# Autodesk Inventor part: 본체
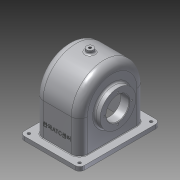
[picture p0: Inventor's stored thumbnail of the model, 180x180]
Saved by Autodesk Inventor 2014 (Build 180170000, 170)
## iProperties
Created: 2016-01
Part Number: 본체
Material: Aluminum 6061
Document SubType Name: Modeling
Designer: user
Density: 2.71 g/cm^3
Appearance: Aluminum - Flat
Mass: 812.573 g
Surface Area: 1007.61 cm^2
Volume: 299.842 cm^3
Author: user
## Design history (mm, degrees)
sketch "Sketch1"
  geometry: 1 further point
sketch "Sketch2"
  geometry: L1 (-57, 4)-(-57, -60); L2 (-57, -60)-(57, -60); L3 (57, -60)-(57, 4); A1 r 57 centre (0, 4) between (-57, 4) and (57, 4); 1 further point
  constraints: 6 end point, 2 perpendicular, 2 point on circle, 2 tangent, 1 centre point, 1 vertical, 1 vertical alignment
  dimensions: "d1" = 114 diameter of A1; "d3" = 60 distance from line of L2 point (0, 0); "d4" = 64 distance from line of L2 A1.centre
extrude "Extrusion1" new body sketch "Sketch2" stored distance "d5" = 77; taper "d6" = 0 deg
sketch "Sketch3"
  geometry: C1 r 31 at (0, 0); 1 further point
  constraints: 1 centre point, 1 coincident
  dimensions: "d7" = 62 diameter of C1
extrude "Extrusion2" join sketch "Sketch3" distance "d8" = 10; taper "d9" = 0 deg
workplane "Work Plane1"
sketch "Sketch4"
  geometry: C1 r 6 at (0, 0); 1 further point
  constraints: 1 centre point, 1 coincident
  dimensions: "d11" = 12 diameter of C1
extrude "Extrusion3" join sketch "Sketch4" stored distance "d12" = 6; taper "d13" = 0 deg
sketch "Sketch5"
  geometry: L1 (-13.5, 13)-(90.5, 13); L2 (90.5, 13)-(90.5, -127); L3 (90.5, -127)-(-13.5, -127); L4 (-13.5, -127)-(-13.5, 13); L5 (-13.5, 13)-(90.5, -127); L6 (90.5, 13)-(-13.5, -127); 1 further point
  constraints: 12 end point, 2 midpoint, 2 parallel, 1 horizontal, 1 perpendicular
  dimensions: "d14" = 104 distance of L1.start L1.end; "d15" = 140 distance of L1.end L2.end
extrude "Extrusion4" join sketch "Sketch5" distance "d16" = 7; taper "d17" = 0 deg
sketch "Sketch6"
  geometry: L1 (-57, -53)-(-57, 4) reference; L2 (57, 4)-(57, -53) reference; L3 (70, -60)-(-70, -60) reference; L4 (-51, -60)-(-51, 4); L5 (51, 4)-(51, -60); L6 (-51, -60)-(51, -60); A1 r 57 centre (0, 4) between (57, 4) and (-57, 4) reference; A2 r 51 centre (0, 4) between (51, 4) and (-51, 4); 1 further point
  constraints: 6 end point, 2 point on circle, 2 point on line, 1 centre point, 1 collinear
  dimensions: "d18" = 6 radial gap between concentric circles of A2 A1; "d19" = 6 distance between parallel lines of L4 L1; "d20" = 6 distance between parallel lines of L2 L5
extrude "Extrusion5" cut sketch "Sketch6" stored distance "d21" = 67; taper "d22" = 0 deg
sketch "Sketch7"
  geometry: C1 r 28 at (0, 0); 1 further point
  constraints: 1 centre point, 1 coincident
  dimensions: "d23" = 56 diameter of C1
extrude "Extrusion6" join sketch "Sketch7" distance "d24" = 14; taper "d25" = 0 deg
feature "FaceDraft1" dims angle "d26" = 40 deg
sketch "Sketch9"
  geometry: C1 r 20 at (0, 0); 1 further point
  constraints: 1 centre point, 1 coincident
  dimensions: "d27" = 40 diameter of C1
extrude "Extrusion7" cut sketch "Sketch9" distance "d28" = 16; taper "d29" = 0 deg
sketch "Sketch10"
  geometry: L1 (33.5, 39.747)-(19.5, 28) reference; L2 (38.5, 37.416)-(35.5, 34.899); L3 (38.5, 4)-(38.5, 61) reference; L4 (38.5, 37.416)-(38.5, 0); L5 (38.5, 0)-(35.5, 0); L6 (35.5, 0)-(35.5, 34.899); 1 further point
  constraints: 8 end point, 2 parallel, 2 point on line, 1 horizontal alignment, 1 perpendicular
  dimensions: "d30" = 5 distance between parallel lines of L2 L1; "d31" = 3 distance between parallel lines of L4 L6
revolve "Revolution1" sketch "Sketch10" stored, may be unused: angle "d32" = 90 deg
sketch "Sketch11"
  geometry: C1 r 20 at (0, 0); 1 further point
  constraints: 1 centre point, 1 coincident
  dimensions: "d33" = 40 diameter of C1
extrude "Extrusion8" cut sketch "Sketch11" distance "d34" = 15; taper "d35" = 0 deg
hole "Hole1" diameter "d38" = 4.459; stored, may be unused: countersink angle "d42" = 90 deg, drill point angle "d44" = 118 deg; dims "d36" = 10, "d37" = 10, "d39" = 6, "d40" = 4, "d41" = 2, "d43" = 8
sketch "Sketch12" dims "d45" = 56
  geometry: L1 (0, 0)-(32.111, 0); 2 further points
  constraints: 2 end point, 1 coincident, 1 horizontal, 1 horizontal alignment, 1 point on line, 2 other
hole "Hole2" sketch "Sketch12" at (28, 0) diameter "d46" = 2.459; stored, may be unused: countersink angle "d50" = 90 deg, drill point angle "d52" = 120 deg; dims "d47" = 7, "d48" = 4, "d49" = 2, "d51" = 9
pattern_circular "Circular Pattern1" dims angle "d54" = 360 deg
sketch "Sketch13" dims "d56" = 48
  geometry: L1 (0, 0)-(-29.155, 0); 2 further points
  constraints: 2 end point, 1 coincident, 1 horizontal, 1 horizontal alignment, 1 point on line, 2 other
hole "Hole3" sketch "Sketch13" at (-24, 0) diameter "d57" = 2.459; stored, may be unused: countersink angle "d61" = 90 deg, drill point angle "d63" = 120 deg; dims "d58" = 6, "d59" = 4, "d60" = 2, "d62" = 8
pattern_circular "Circular Pattern2" dims angle "d65" = 360 deg
sketch "Sketch14"
  geometry: L1 (-63.125, -34)-(140.125, -34); L2 (38.5, -23.832)-(38.5, -44.168); L3 (-13.5, -64)-(90.5, -64) reference; L4 (0, -57)-(0, 0) reference; 4 further points
  constraints: 4 end point, 2 midpoint, 1 coincident, 1 horizontal, 1 perpendicular, 1 vertical alignment, 1 other
  dimensions: "d67" = 30 distance between parallel lines of L3 L1; "d68" = 38.5 distance between parallel lines of L2 L4 (derived)
emboss "Emboss1" sketch "Sketch14" dims "d69" = 0.5, "d70" = 0
fillet "Fillet1" dims "d71" = 3
sketch "Sketch15"
  geometry: L1 (-82.5, 5)-(5.5, 5); L2 (5.5, 5)-(5.5, -119); L3 (5.5, -119)-(-82.5, -119); L4 (-82.5, -119)-(-82.5, 5); L5 (-82.5, 5)-(5.5, -119); L6 (5.5, 5)-(-82.5, -119); 5 further points
  constraints: 12 end point, 4 coincident, 2 midpoint, 2 parallel, 1 horizontal, 1 perpendicular
  dimensions: "d72" = 124 distance of L1.end L2.end; "d73" = 44 distance from line of point (-38.5, -57) L2
hole "Hole4" sketch "Sketch15" at (-82.5, -119), (5.5, -119), (5.5, 5), (-82.5, 5) diameter "d74" = 5; stored, may be unused: countersink angle "d78" = 90 deg, drill point angle "d80" = 0 deg; dims "d75" = 6, "d76" = 4, "d77" = 2, "d79" = 8
fillet "Fillet2" dims "d81" = 8
fillet "Fillet3" dims "d82" = 14
fillet "Fillet4" dims "d83" = 9
fillet "Fillet5" dims "d84" = 3
fillet "Fillet6" dims "d85" = 1
fillet "Fillet7" dims "d86" = 3
chamfer "Chamfer1" distance "d87" = 1; stored, may be unused: second distance "d88" = 2, angle "d89" = 45 deg
body "Solid1"
other parameters: "d10" = 67
